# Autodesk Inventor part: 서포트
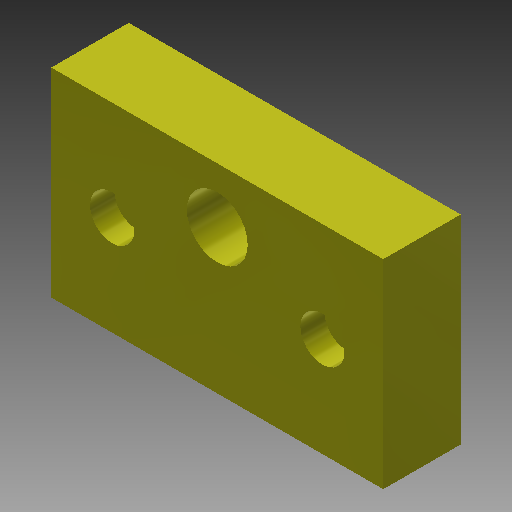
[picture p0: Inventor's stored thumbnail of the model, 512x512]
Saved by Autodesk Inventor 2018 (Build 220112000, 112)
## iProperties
Created: 2020-03
Part Number: 서포트
Material: 일반
Document SubType Name: Modeling
Designer: mduedu
Density: 1 g/cm^3
Mass: 27.2068 g
Surface Area: 81.0378 cm^2
Volume: 27.2068 cm^3
Appearance: 노란색
Author: mduedu
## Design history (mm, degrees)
sketch "스케치1"
  geometry: L1 (-30, 0)-(30, 0); L2 (30, 0)-(30, 36); L3 (30, 36)-(-30, 36); L4 (-30, 36)-(-30, 0); 2 further points
  constraints: 8 end point, 2 parallel, 1 coincident, 1 horizontal, 1 midpoint, 1 perpendicular
  dimensions: "d0" = 60 distance of L1.start L1.end; "d2" = 36 distance of L1.end L2.end
extrude "돌출1" new body sketch "스케치1" distance "d3" = 14; taper "d4" = 0 deg
sketch "스케치2"
  geometry: 3 further points
  constraints: 1 horizontal alignment
  dimensions: "d5" = 7 vertical distance of point (52, 7) point (30, 0); "d6" = 22 horizontal distance of point (8, 7) point (30, 0); "d7" = 44 distance of point (52, 7) point (8, 7)
hole "구멍1" sketch "스케치2" at (8, 7), (52, 7) diameter "d8" = 3.242; stored, may be unused: countersink angle "d12" = 90 deg, drill point angle "d14" = 118 deg; dims "d9" = 6, "d10" = 4, "d11" = 2, "d13" = 8
sketch "스케치3"
  geometry: L1 (30, 0)-(-30, 0) reference; 3 further points
  constraints: 1 midpoint, 1 vertical alignment
  dimensions: "d15" = 26 distance of point (0, 0) point (0, 26)
hole "구멍2" sketch "스케치3" at (0, 26) diameter "d16" = 11; stored, may be unused: countersink angle "d20" = 90 deg, drill point angle "d22" = 118 deg; dims "d17" = 8, "d18" = 15, "d19" = 3, "d21" = 10
sketch "스케치4"
  geometry: 3 further points
  constraints: 1 horizontal alignment
  dimensions: "d23" = 18 vertical distance of point (19, 18) point (0, 0); "d24" = 19 horizontal distance of point (-19, 18) point (0, 0); "d25" = 38 distance of point (19, 18) point (-19, 18)
hole "구멍3" sketch "스케치4" at (-19, 18), (19, 18) diameter "d26" = 4.5; stored, may be unused: countersink angle "d30" = 90 deg, drill point angle "d32" = 118 deg; dims "d27" = 8, "d28" = 8, "d29" = 4.4, "d31" = 10
sketch "스케치5"
  geometry: C1 r 2.25 at (-19, 18) reference; 1 further point
hole "구멍4" sketch "스케치5" at (-19, 18) diameter "d33" = 9; stored, may be unused: countersink angle "d37" = 90 deg, drill point angle "d39" = 0 deg; dims "d34" = 8, "d35" = 8, "d36" = 4.4, "d38" = 6
sketch "스케치6"
  geometry: C1 r 2.25 at (19, 18) reference; 1 further point
hole "구멍5" sketch "스케치6" at (19, 18) diameter "d40" = 9; stored, may be unused: countersink angle "d44" = 90 deg, drill point angle "d46" = 0 deg; dims "d41" = 8, "d42" = 8, "d43" = 4.4, "d45" = 6
node "솔리드1"
